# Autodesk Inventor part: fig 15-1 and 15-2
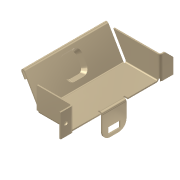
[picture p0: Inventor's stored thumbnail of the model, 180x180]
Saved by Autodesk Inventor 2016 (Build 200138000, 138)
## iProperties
Shininess: 65.0
Angle Display Precision: 2
Document Length Units: 11269
Document Angle Units: 11279
Document Time Units: 11290
Document Mass Units: 11283
Document Length Units Precision: 3
Document Angle Units Precision: 2
Compacted: False
Created: 2002-04
Part Number: fig 15-1 and 15-2
Material: Stainless Steel, 440C
Document SubType Name: Sheet Metal
Density: 1 g/cm^3
Sheet Metal Rule: Default
Appearance: Metal-Titanium (Polished)
Density: 0.0
Volumn: 0.0
Area: 0.0
PropertySet Name: Model Information
Control State: 0
Master: False
Checked Out: False
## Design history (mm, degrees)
node "Face1"
  sketch "Sketch1"
    geometry: L1 (-46.618, 22.343)-(-46.618, -12.657); L2 (-46.618, -12.657)-(53.382, -12.657); L3 (53.382, -12.657)-(53.382, 22.343); L4 (53.382, 22.343)-(35.882, 22.343); L5 (35.882, 22.343)-(35.882, 12.343); L6 (35.882, 12.343)-(-29.118, 12.343); L7 (-29.118, 12.343)-(-29.118, 22.343); L8 (-29.118, 22.343)-(-46.618, 22.343)
    constraints: 16 end point, 6 parallel, 2 equal length, 1 perpendicular, 1 vertical
    dimensions: "d0" = 100 distance of L1.end L2.end; "d1" = 35 distance of L1.start L1.end; "d2" = 65 distance of L5.end L6.end; "d3" = 10 distance of L6.end L7.end
sketch "Sketch2"
  geometry: L1 (100, 0)-(0, 0) reference; L2 (17.5, 35)-(17.5, 25) reference; L3 (17.5, 25)-(17.5, 0); L4 (82.5, 25)-(82.5, 0)
  constraints: 4 end point, 2 point on line, 1 collinear, 1 perpendicular
feature "Fold1" dims "d5" = 1 (= BendRadius), "d6" = 90 deg, "d7" = 1 (= BendRadius), "d52" = 1 (= BendReliefWidth), "d53" = 0.5 (= BendReliefDepth), "d54" = 2 (= MinimumRemnant), "SeamGap" = 0.01, "Thickness" = 1
feature "Fold2" dims "d8" = 1 (= BendRadius), "d9" = 90 deg, "d10" = 1 (= BendRadius), "d55" = 1 (= BendReliefWidth), "d56" = 0.5 (= BendReliefDepth), "d57" = 2 (= MinimumRemnant), "SeamGap" = 0.01, "Thickness" = 1
node "Flange1"
feature "Corner1" dims "d15" = 1 (= Thickness), "d16" = 0, "d73" = 4 (= CornerReliefSize), "Thickness" = 1, "TransitionRadius" = 1 (= BendRadius)
sketch "Sketch4"
  geometry: L1 (0, 0)-(0, 35) reference; L2 (15.869, 25)-(15.869, 26) reference; L3 (17.5, 26)-(0, 26)
  constraints: 2 end point, 1 perpendicular, 1 point on line
feature "Fold3" sketch "Sketch4" dims "d17" = 1 (= BendRadius), "d18" = 90 deg, "d19" = 1 (= BendRadius), "d61" = 1 (= BendReliefWidth), "d62" = 0.5 (= BendReliefDepth), "d63" = 2 (= MinimumRemnant), "SeamGap" = 0.01, "Thickness" = 1
sketch "Sketch5"
  geometry: L1 (-17.5, -34.296)-(-17.5, 9) reference; L2 (0, 0)-(-17.5, 0)
  constraints: 2 end point, 1 perpendicular, 1 point on line
feature "Fold4" sketch "Sketch5" dims "d20" = 1 (= BendRadius), "d21" = 90 deg, "d22" = 1 (= BendRadius), "d64" = 1 (= BendReliefWidth), "d65" = 0.5 (= BendReliefDepth), "d66" = 2 (= MinimumRemnant), "SeamGap" = 0.01, "Thickness" = 1
sketch "Sketch6"
  geometry: 1 further point
feature "iFeature4:1" sketch "Sketch6"
feature "Hem2" dims "d32" = 1 (= BendRadius), "d33" = 6 (= 6 x Thickness), "d34" = 1 (= Thickness), "d35" = 0.5 (= 0.5 x d34), "d67" = 1 (= BendReliefWidth), "d68" = 0.5 (= BendReliefDepth), "d69" = 2 (= MinimumRemnant), "SeamGap" = 0.01, "Thickness" = 1, "MinimumRemnant" = 2 (= 2 x Thickness), "BendReliefWidth" = 1 (= Thickness)
node "Face2"
  sketch "Sketch9"
    geometry: L1 (0, 0)-(62.738, 0) reference; L2 (40.511, 0)-(22.35, 0); L3 (22.35, 0)-(22.35, 18.987); L4 (22.35, 18.987)-(40.511, 18.987); L5 (40.511, 18.987)-(40.511, 0)
    constraints: 8 end point, 2 parallel, 1 horizontal, 1 perpendicular, 1 point on line
sketch "Sketch10"
  geometry: L1 (13.661, -2.202)-(4.661, -2.202); L2 (4.661, -2.202)-(4.661, -7.127); L3 (4.661, -7.127)-(13.661, -7.127); L4 (13.661, -7.127)-(13.661, -2.202); L5 (18.161, -16.987)-(18.161, 0) reference
  constraints: 8 end point, 2 parallel, 1 horizontal, 1 perpendicular
  dimensions: "d50" = 4.5 distance between parallel lines of L5 L4; "d51" = 9 distance of L1.start L1.end
cut "Cut1" sketch "Sketch10" dims "d38" = 1 (= Thickness), "d39" = 0
sketch "Sketch11"
  geometry: 1 further point
hole "Hole1" sketch "Sketch11" at (3.935, 8.75) diameter "d40" = 3; stored, may be unused: countersink angle "d44" = 82 deg, drill point angle "d46" = 118 deg; dims "d41" = 6, "d42" = 4, "d43" = 2, "d45" = 8
feature "Corner Chamfer1" dims "d47" = 6, "d48" = 6, angle "d74" = 45 deg
feature "Corner Round1" dims "d49" = 6
body "Solid1"
face "Plate1" dims "Thickness" = 1
sketch "Sketch3"
  geometry: L1 through (-31.369, 0) direction (-1, -6.59e-18); L2 (-62.738, 0)-(-62.738, 25); L3 (-62.738, 25)-(0, 25); L4 through (0, 12.5) direction (-1.11e-17, -1)
  constraints: 6 end point, 1 horizontal, 1 perpendicular, 1 vertical
face "Plate2" dims "d12" = 25, "d13" = 120 deg, "d14" = 1 (= BendRadius), "Thickness" = 1, "MinimumRemnant" = 2 (= 2 x Thickness), "BendReliefWidth" = 1 (= Thickness)
bend "Bend1" dims "d11" = 1 (= BendRadius), "d12" = 25, "d13" = 120 deg, "d14" = 1 (= BendRadius), "d58" = 1 (= BendReliefWidth), "d59" = 0.5 (= BendReliefDepth), "d60" = 2 (= MinimumRemnant), "SeamGap" = 0.01, "Thickness" = 1, "MinimumRemnant" = 2 (= 2 x Thickness), "BendReliefWidth" = 1 (= Thickness)
sketch "Sketch8"
  geometry: L1 (0.866, 0.5)-(0, 0); L2 (-0.866, -0.5)-(1.384, -4.397); L3 (1.384, -4.397)-(0.518, -4.897); L4 (0.518, -4.897)-(-1.732, -1); A1 r 0.5 centre (-0.433, -0.25) between (0, 0) and (-0.866, -0.5); A2 r 1.5 centre (-0.433, -0.25) between (0.866, 0.5) and (-1.732, -1)
  constraints: 8 end point, 4 point on circle
face "Plate3" dims "d36" = 1 (= BendRadius), "Thickness" = 1, "MinimumRemnant" = 2 (= 2 x Thickness), "BendReliefWidth" = 1 (= Thickness)
bend "Bend2" dims "d36" = 1 (= BendRadius), "d37" = 1 (= BendRadius), "d70" = 1 (= BendReliefWidth), "d71" = 0.5 (= BendReliefDepth), "d72" = 2 (= MinimumRemnant), "SeamGap" = 0.01, "Thickness" = 1, "MinimumRemnant" = 2 (= 2 x Thickness), "BendReliefWidth" = 1 (= Thickness)
other parameters: "BendRadius" = 1 (= Thickness), "BendReliefDepth" = 0.5 (= 0.5 x Thickness), "CornerReliefSize" = 4 (= 4 x Thickness), "d4" = 1 (= BendRadius), "d27" = 0, "JacobiRadiusSize" = 1 (= Thickness), "GapSize" = 1 (= Thickness)
